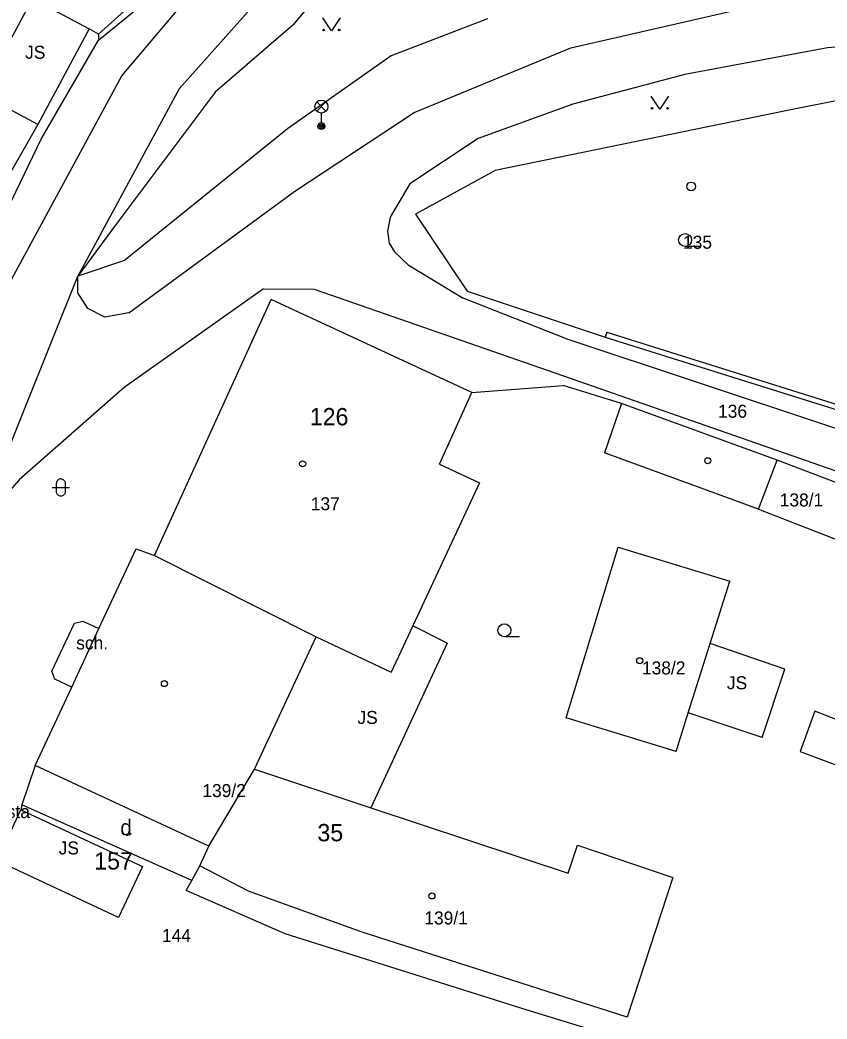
# Model space of a CAD drawing. Extents: x -836739 to -835945, y -1070775 to -1070126.
# Drawn here: x -836621.5 to -836574.9, y -1070420 to -1070362.4 of the extents above; entities that cross this region are included whole.
import ezdxf

# ---------------------------------------------------------------- set-up
doc = ezdxf.new("R2010")
doc.units = 0
for name, color, linetype in [('BodPole_mer', 7, 'Continuous'), ('Budovy_hranice', 7, 'Continuous'), ('Budovy_kody', 7, 'Continuous'), ('Doprava_hranice', 7, 'Continuous'), ('Doprava_kody', 7, 'Continuous'), ('OstPloch_hranice', 7, 'Continuous'), ('OstPloch_kody', 7, 'Continuous'), ('PovrZnIS_body', 7, 'Continuous'), ('RuianAdr_popis', 7, 'Continuous'), ('RuianPar_popis', 7, 'Continuous'), ('Stavby_hr_schod', 7, 'Continuous'), ('Stavby_hr_stav', 7, 'Continuous'), ('Stavby_kody', 7, 'Continuous'), ('Stavby_linie', 7, 'Continuous'), ('Zelen_kody', 7, 'Continuous')]:
    doc.layers.add(name, color=color, linetype=linetype)

msp = doc.modelspace()

# ---------------------------------------------------------------- linework, layer by layer
at = {"layer": 'BodPole_mer'}
for p, q in [((-836617.48, -1070362.88), (-836617.48, -1070362.88)), ((-836605.7, -1070362.64), (-836605.7, -1070362.64)), ((-836617.61, -1070363.13), (-836617.61, -1070363.13)), ((-836616.94, -1070363.17), (-836616.94, -1070363.17)), ((-836616.94, -1070363.53), (-836616.94, -1070363.53)), ((-836589.69, -1070363.97), (-836589.69, -1070363.97)), ((-836600.06, -1070364.43), (-836600.06, -1070364.43)), ((-836615.6, -1070365.58), (-836615.6, -1070365.58)), ((-836583.1, -1070365.51), (-836583.1, -1070365.51)), ((-836612.29, -1070366.34), (-836612.29, -1070366.34)), ((-836610.22, -1070366.53), (-836610.22, -1070366.53)), ((-836598.73, -1070367.69), (-836598.73, -1070367.69)), ((-836589.57, -1070367.22), (-836589.57, -1070367.22)), ((-836577.37, -1070367.63), (-836577.37, -1070367.63)), ((-836620.44, -1070368.4), (-836620.44, -1070368.4)), ((-836606.04, -1070368.64), (-836606.04, -1070368.64)), ((-836604.08, -1070368.48), (-836604.08, -1070368.48)), ((-836620.25, -1070369.24), (-836620.25, -1070369.24)), ((-836595.04, -1070369.19), (-836595.04, -1070369.19)), ((-836594.06, -1070371.04), (-836594.06, -1070371.04)), ((-836605.62, -1070372.23), (-836605.62, -1070372.23)), ((-836598.97, -1070371.82), (-836598.97, -1070371.82)), ((-836582.74, -1070371.96), (-836582.74, -1070371.96)), ((-836600.12, -1070373.74), (-836600.12, -1070373.74)), ((-836598.65, -1070373.57), (-836598.65, -1070373.57)), ((-836615.99, -1070374.22), (-836615.99, -1070374.22)), ((-836600.26, -1070374.54), (-836600.26, -1070374.54)), ((-836600.16, -1070375.24), (-836600.16, -1070375.24)), ((-836599.87, -1070375.74), (-836599.87, -1070375.74)), ((-836615.44, -1070376.23), (-836615.44, -1070376.23)), ((-836599.07, -1070376.48), (-836599.07, -1070376.48)), ((-836618.13, -1070377.15), (-836618.13, -1070377.15)), ((-836618.13, -1070378.1), (-836618.13, -1070378.1)), ((-836607.42, -1070377.87), (-836607.42, -1070377.87)), ((-836604.5, -1070377.9), (-836604.5, -1070377.9)), ((-836595.66, -1070378.01), (-836595.66, -1070378.01)), ((-836606.98, -1070378.49), (-836606.98, -1070378.49)), ((-836595.9, -1070378.41), (-836595.9, -1070378.41)), ((-836617.56, -1070379.01), (-836617.56, -1070379.01)), ((-836615.19, -1070379.26), (-836615.19, -1070379.26)), ((-836616.58, -1070379.5), (-836616.58, -1070379.5)), ((-836587.61, -1070380.37), (-836587.61, -1070380.37)), ((-836589.83, -1070380.79), (-836589.83, -1070380.79)), ((-836587.7, -1070380.66), (-836587.7, -1070380.66)), ((-836590.11, -1070382.9), (-836590.11, -1070382.9)), ((-836615.46, -1070383.56), (-836615.46, -1070383.56)), ((-836595.39, -1070383.86), (-836595.39, -1070383.86)), ((-836590.12, -1070383.45), (-836590.12, -1070383.45)), ((-836586.76, -1070384.49), (-836586.76, -1070384.49)), ((-836587.74, -1070387.34), (-836587.74, -1070387.34)), ((-836577.78, -1070387.76), (-836577.78, -1070387.76)), ((-836597.27, -1070387.99), (-836597.27, -1070387.99)), ((-836594.95, -1070389.07), (-836594.95, -1070389.07)), ((-836578.85, -1070390.58), (-836578.85, -1070390.58)), ((-836614.77, -1070392.87), (-836614.77, -1070392.87)), ((-836586.96, -1070392.78), (-836586.96, -1070392.78)), ((-836613.72, -1070393.26), (-836613.72, -1070393.26)), ((-836580.5, -1070394.75), (-836580.5, -1070394.75)), ((-836617.84, -1070397.05), (-836617.84, -1070397.05)), ((-836618.33, -1070397.16), (-836618.33, -1070397.16)), ((-836616.92, -1070397.47), (-836616.92, -1070397.47)), ((-836598.8, -1070397.31), (-836598.8, -1070397.31)), ((-836604.39, -1070397.96), (-836604.39, -1070397.96)), ((-836596.82, -1070398.31), (-836596.82, -1070398.31)), ((-836581.64, -1070398.34), (-836581.64, -1070398.34)), ((-836619.63, -1070399.94), (-836619.63, -1070399.94)), ((-836600.05, -1070399.99), (-836600.05, -1070399.99)), ((-836577.33, -1070399.82), (-836577.33, -1070399.82)), ((-836619.47, -1070400.39), (-836619.47, -1070400.39)), ((-836618.49, -1070400.85), (-836618.49, -1070400.85)), ((-836575.61, -1070402.24), (-836575.61, -1070402.24)), ((-836589.95, -1070402.63), (-836589.95, -1070402.63)), ((-836582.91, -1070402.34), (-836582.91, -1070402.34)), ((-836578.65, -1070403.77), (-836578.65, -1070403.77)), ((-836583.61, -1070404.56), (-836583.61, -1070404.56)), ((-836576.45, -1070404.57), (-836576.45, -1070404.57)), ((-836620.6, -1070405.38), (-836620.6, -1070405.38)), ((-836607.95, -1070405.59), (-836607.95, -1070405.59)), ((-836621.42, -1070407.93), (-836621.42, -1070407.93)), ((-836621.36, -1070407.64), (-836621.36, -1070407.64)), ((-836601.23, -1070407.82), (-836601.23, -1070407.82)), ((-836610.58, -1070410.04), (-836610.58, -1070410.04)), ((-836589.3, -1070409.98), (-836589.3, -1070409.98)), ((-836592.75, -1070410.62), (-836592.75, -1070410.62)), ((-836592.46, -1070410.72), (-836592.46, -1070410.72)), ((-836614.41, -1070411.21), (-836614.41, -1070411.21)), ((-836611.1, -1070411.16), (-836611.1, -1070411.16)), ((-836611.56, -1070412.01), (-836611.56, -1070412.01)), ((-836589.84, -1070411.58), (-836589.84, -1070411.58)), ((-836583.79, -1070411.84), (-836583.79, -1070411.84)), ((-836611.88, -1070412.58), (-836611.88, -1070412.58)), ((-836608.28, -1070412.62), (-836608.28, -1070412.62)), ((-836615.78, -1070414.14), (-836615.78, -1070414.14)), ((-836601.79, -1070414.98), (-836601.79, -1070414.98)), ((-836606.18, -1070415.08), (-836606.18, -1070415.08)), ((-836592.27, -1070419.48), (-836592.27, -1070419.48)), ((-836586.43, -1070419.9), (-836586.43, -1070419.9))]:
    msp.add_line(p, q, dxfattribs=at)
at = {"layer": 'Budovy_hranice'}
for p, q in [((-836613.72, -1070393.26), (-836606.98, -1070378.49)), ((-836595.39, -1070383.86), (-836606.98, -1070378.49)), ((-836597.27, -1070387.99), (-836595.39, -1070383.86)), ((-836586.76, -1070384.49), (-836587.74, -1070387.34)), ((-836577.78, -1070387.76), (-836586.76, -1070384.49)), ((-836578.85, -1070390.58), (-836587.74, -1070387.34)), ((-836578.85, -1070390.58), (-836577.78, -1070387.76)), ((-836566.92, -1070391.9), (-836577.78, -1070387.76)), ((-836597.27, -1070387.99), (-836594.95, -1070389.07)), ((-836589.95, -1070402.63), (-836586.96, -1070392.78)), ((-836586.96, -1070392.78), (-836580.5, -1070394.75)), ((-836604.39, -1070397.96), (-836600.05, -1070399.99)), ((-836583.61, -1070404.56), (-836589.95, -1070402.63)), ((-836589.84, -1070411.58), (-836589.3, -1070409.98)), ((-836589.3, -1070409.98), (-836583.79, -1070411.84)), ((-836583.79, -1070411.84), (-836586.43, -1070419.9)), ((-836601.79, -1070414.98), (-836608.28, -1070412.62)), ((-836586.43, -1070419.9), (-836601.79, -1070414.98))]:
    msp.add_line(p, q, dxfattribs=at)
for points in [[(-836594.95, -1070389.07), (-836598.8, -1070397.31), (-836600.05, -1070399.99)], [(-836578.85, -1070390.58), (-836572.88, -1070392.92), (-836567.83, -1070394.89)], [(-836610.58, -1070410.04), (-836620.6, -1070405.38), (-836618.49, -1070400.85), (-836616.92, -1070397.47), (-836614.77, -1070392.87), (-836613.72, -1070393.26), (-836604.39, -1070397.96)], [(-836583.61, -1070404.56), (-836582.91, -1070402.34), (-836581.64, -1070398.34), (-836580.5, -1070394.75)], [(-836608.28, -1070412.62), (-836611.1, -1070411.16), (-836610.58, -1070410.04), (-836607.95, -1070405.59), (-836604.39, -1070397.96)], [(-836570.76, -1070404.11), (-836574.08, -1070402.83), (-836575.61, -1070402.24), (-836576.45, -1070404.57), (-836571.47, -1070406.44), (-836570.76, -1070404.11)], [(-836607.95, -1070405.59), (-836601.23, -1070407.82), (-836592.75, -1070410.62), (-836592.46, -1070410.72), (-836589.84, -1070411.58)]]:
    msp.add_lwpolyline(points, dxfattribs=at)
at = {"layer": 'Budovy_kody'}
for centre in [(-836605.16, -1070387.97), (-836581.78, -1070387.79), (-836585.71, -1070399.33), (-836613.14, -1070400.65), (-836597.7, -1070412.9)]:
    msp.add_circle(centre, 0.175, dxfattribs=at)
at = {"layer": 'Doprava_hranice'}
msp.add_line((-836624, -1070391.72), (-836618.13, -1070377.15), dxfattribs=at)
for points in [[(-836637.13, -1070410.36), (-836632.54, -1070399.93), (-836624.1, -1070381.23), (-836615.6, -1070365.58), (-836607.14, -1070355.56), (-836596.81, -1070346.2), (-836590.03, -1070339.5), (-836589.31, -1070338.79), (-836589.07, -1070337.69), (-836589.06, -1070336.43), (-836589.28, -1070334.96), (-836590.73, -1070333.14), (-836591.73, -1070332.35), (-836593.66, -1070331.61), (-836605.86, -1070329.36), (-836624.31, -1070324.48)], [(-836615.19, -1070379.26), (-836605.62, -1070372.23), (-836598.73, -1070367.69), (-836589.69, -1070363.97), (-836577.99, -1070361.29), (-836567.54, -1070359.78), (-836561.76, -1070359.47), (-836555.57, -1070359.6), (-836542.56, -1070361.3), (-836539.53, -1070361.13), (-836537.36, -1070360.46), (-836536.61, -1070359.71), (-836537.63, -1070358), (-836543.83, -1070354.6), (-836550.65, -1070351.53), (-836553.41, -1070349.94), (-836556.85, -1070346.77), (-836557.71, -1070345.9), (-836560.14, -1070342.4), (-836564.87, -1070335.97), (-836569.41, -1070333.94)], [(-836589.25, -1070343.85), (-836600.64, -1070354.35), (-836606.73, -1070360.09), (-836612.29, -1070366.34), (-836618.13, -1070377.15)], [(-836599.6, -1070356.75), (-836602.09, -1070358.28), (-836605.7, -1070362.64), (-836610.22, -1070366.53), (-836615.99, -1070374.22), (-836618.13, -1070377.15)], [(-836594.49, -1070362.3), (-836600.06, -1070364.43), (-836606.04, -1070368.64), (-836615.44, -1070376.23), (-836618.13, -1070377.15)], [(-836547.65, -1070364.49), (-836556.3, -1070362.82), (-836560.36, -1070362.88), (-836566.97, -1070363.32), (-836574.87, -1070363.96), (-836583.1, -1070365.51), (-836589.57, -1070367.22), (-836595.04, -1070369.19), (-836598.97, -1070371.82)], [(-836598.97, -1070371.82), (-836600.12, -1070373.74), (-836600.26, -1070374.54), (-836600.16, -1070375.24), (-836599.87, -1070375.74), (-836599.07, -1070376.48), (-836595.9, -1070378.41)], [(-836615.19, -1070379.26), (-836616.58, -1070379.5), (-836617.56, -1070379.01), (-836618.13, -1070378.1), (-836618.13, -1070377.15)], [(-836607.42, -1070377.87), (-836615.46, -1070383.56), (-836621.52, -1070388.89), (-836624, -1070391.72)], [(-836607.42, -1070377.87), (-836604.5, -1070377.9), (-836590.11, -1070382.9), (-836566.68, -1070391.06)], [(-836567.33, -1070388.27), (-836589.83, -1070380.79), (-836595.9, -1070378.41)]]:
    msp.add_lwpolyline(points, dxfattribs=at)
at = {"layer": 'OstPloch_hranice'}
msp.add_line((-836620.6, -1070405.38), (-836621.36, -1070407.64), dxfattribs=at)
at = {"layer": 'OstPloch_kody'}
for p, q in [((-836582.215, -1070375.43), (-836583.09, -1070375.43)), ((-836619.62, -1070389.34), (-836618.62, -1070389.34)), ((-836619.37, -1070389.59), (-836619.37, -1070389.09)), ((-836618.87, -1070389.09), (-836618.87, -1070389.59)), ((-836592.645, -1070397.95), (-836593.52, -1070397.95))]:
    msp.add_line(p, q, dxfattribs=at)
for points in [[(-836619.12, -1070388.84), (-836619.165, -1070388.844), (-836619.212, -1070388.858), (-836619.257, -1070388.881), (-836619.297, -1070388.913), (-836619.329, -1070388.953), (-836619.352, -1070388.998), (-836619.366, -1070389.045), (-836619.37, -1070389.09)], [(-836619.12, -1070388.84), (-836619.075, -1070388.844), (-836619.028, -1070388.858), (-836618.983, -1070388.881), (-836618.943, -1070388.913), (-836618.911, -1070388.953), (-836618.888, -1070388.998), (-836618.874, -1070389.045), (-836618.87, -1070389.09)], [(-836619.12, -1070389.84), (-836619.165, -1070389.836), (-836619.212, -1070389.822), (-836619.257, -1070389.799), (-836619.297, -1070389.767), (-836619.329, -1070389.727), (-836619.352, -1070389.682), (-836619.366, -1070389.635), (-836619.37, -1070389.59)], [(-836618.87, -1070389.59), (-836618.874, -1070389.635), (-836618.888, -1070389.682), (-836618.911, -1070389.727), (-836618.943, -1070389.767), (-836618.983, -1070389.799), (-836619.028, -1070389.822), (-836619.075, -1070389.836), (-836619.12, -1070389.84)], [(-836615.309, -1070409.4), (-836615.309, -1070409.405), (-836615.308, -1070409.411), (-836615.3, -1070409.415), (-836615.283, -1070409.413), (-836615.253, -1070409.404), (-836615.205, -1070409.383), (-836615.137, -1070409.347), (-836615.044, -1070409.294)]]:
    msp.add_lwpolyline(points, dxfattribs=at)
for centre in [(-836583.09, -1070375.055), (-836593.52, -1070397.575)]:
    msp.add_ellipse(centre, major_axis=(0.375, 0), ratio=0.999999, dxfattribs=at)
at = {"layer": 'PovrZnIS_body'}
for p, q in [((-836604.345, -1070367.62), (-836603.815, -1070367.09)), ((-836604.345, -1070367.09), (-836603.815, -1070367.62)), ((-836604.08, -1070368.28), (-836604.08, -1070367.73))]:
    msp.add_line(p, q, dxfattribs=at)
msp.add_circle((-836582.74, -1070371.96), 0.25, dxfattribs=at)
for centre, major_axis in [((-836604.08, -1070367.355), (0.375, 0)), ((-836604.08, -1070368.48), (0.2, 0)), ((-836604.076, -1070368.48), (0.125, 0)), ((-836604.076, -1070368.48), (0.05, 0))]:
    msp.add_ellipse(centre, major_axis=major_axis, ratio=0.999998, dxfattribs=at)
at = {"layer": 'RuianAdr_popis'}
for p, q in [((-836604.75, -1070385.75), (-836604.75, -1070385.75)), ((-836604.31, -1070409.75), (-836604.31, -1070409.75)), ((-836617.19, -1070411.38), (-836617.19, -1070411.38))]:
    msp.add_line(p, q, dxfattribs=at)
at = {"layer": 'RuianPar_popis'}
for p, q in [((-836583.21, -1070375.56), (-836583.21, -1070375.56)), ((-836581.19, -1070385.31), (-836581.19, -1070385.31)), ((-836604.69, -1070390.65), (-836604.69, -1070390.65)), ((-836577.63, -1070390.43), (-836577.63, -1070390.43)), ((-836585.58, -1070400.12), (-836585.58, -1070400.12)), ((-836610.95, -1070407.2), (-836610.95, -1070407.2)), ((-836598.14, -1070414.55), (-836598.14, -1070414.55)), ((-836613.28, -1070415.56), (-836613.28, -1070415.56))]:
    msp.add_line(p, q, dxfattribs=at)
at = {"layer": 'Stavby_hr_schod'}
msp.add_lwpolyline([(-836618.49, -1070400.85), (-836619.47, -1070400.39), (-836619.63, -1070399.94), (-836618.33, -1070397.16), (-836617.84, -1070397.05), (-836616.92, -1070397.47)], dxfattribs=at)
at = {"layer": 'Stavby_hr_stav'}
for p, q in [((-836587.7, -1070380.66), (-836567.64, -1070386.96)), ((-836596.82, -1070398.31), (-836598.8, -1070397.31)), ((-836596.82, -1070398.31), (-836601.23, -1070407.82)), ((-836578.65, -1070403.77), (-836582.91, -1070402.34))]:
    msp.add_line(p, q, dxfattribs=at)
for points in [[(-836620.44, -1070368.4), (-836623.72, -1070366.64), (-836620.75, -1070361.12), (-836620.48, -1070361.27), (-836617.48, -1070362.88), (-836617.61, -1070363.13), (-836620.44, -1070368.4)], [(-836578.65, -1070403.77), (-836577.33, -1070399.82), (-836581.64, -1070398.34)], [(-836621.42, -1070407.93), (-836614.41, -1070411.21), (-836615.78, -1070414.14), (-836622.8, -1070410.87), (-836621.81, -1070408.77), (-836621.42, -1070407.93)]]:
    msp.add_lwpolyline(points, dxfattribs=at)
at = {"layer": 'Stavby_linie'}
for p, q in [((-836616.94, -1070363.17), (-836617.48, -1070362.88)), ((-836587.61, -1070380.37), (-836587.7, -1070380.66)), ((-836587.61, -1070380.37), (-836567.72, -1070386.62)), ((-836595.39, -1070383.86), (-836590.12, -1070383.45)), ((-836586.76, -1070384.49), (-836590.12, -1070383.45))]:
    msp.add_line(p, q, dxfattribs=at)
for points in [[(-836608.79, -1070352.5), (-836611.63, -1070356.68), (-836613.95, -1070360.46), (-836616.94, -1070363.17), (-836616.94, -1070363.53)], [(-836616.94, -1070363.53), (-836613.84, -1070360.99), (-836608.56, -1070352.7)], [(-836626.49, -1070382.25), (-836624.37, -1070377.75), (-836620.25, -1070369.24), (-836616.94, -1070363.53)], [(-836573.6, -1070366.88), (-836577.37, -1070367.63), (-836594.06, -1070371.04), (-836598.65, -1070373.57), (-836595.66, -1070378.01), (-836587.7, -1070380.66)], [(-836620.44, -1070368.4), (-836622.88, -1070372.65), (-836625.16, -1070377.26)], [(-836611.56, -1070412.01), (-836621.36, -1070407.64), (-836621.42, -1070407.93)], [(-836574.93, -1070422.97), (-836582.62, -1070420.71), (-836583.02, -1070422.31), (-836592.27, -1070419.48), (-836606.18, -1070415.08), (-836611.88, -1070412.58), (-836611.56, -1070412.01), (-836611.1, -1070411.16)]]:
    msp.add_lwpolyline(points, dxfattribs=at)
at = {"layer": 'Zelen_kody'}
for points in [[(-836603, -1070362.24), (-836603.5, -1070362.99), (-836604, -1070362.24)], [(-836584.05, -1070366.76), (-836584.55, -1070367.51), (-836585.05, -1070366.76)]]:
    msp.add_lwpolyline(points, dxfattribs=at)
for centre in [(-836603.949, -1070362.94), (-836603.049, -1070362.94), (-836584.999, -1070367.46), (-836584.099, -1070367.46)]:
    msp.add_circle(centre, 0.05, dxfattribs=at)

# ---------------------------------------------------------------- texts
at = {"layer": 'Doprava_kody'}
msp.add_text('nezp.cesta', height=0.75, dxfattribs=at).set_placement((-836625.75, -1070408.41))
at = {"layer": 'OstPloch_kody'}
msp.add_text('d', height=0.9, dxfattribs=at).set_placement((-836615.685, -1070409.4))
at = {"layer": 'RuianAdr_popis'}
for s, p in [('126', (-836604.75, -1070385.75)), ('35', (-836604.31, -1070409.75)), ('157', (-836617.19, -1070411.38))]:
    msp.add_text(s, height=1, dxfattribs=at).set_placement(p)
at = {"layer": 'RuianPar_popis'}
for s, p in [('135', (-836583.21, -1070375.56)), ('136', (-836581.19, -1070385.31)), ('138/1', (-836577.63, -1070390.43)), ('137', (-836604.69, -1070390.65)), ('138/2', (-836585.58, -1070400.12)), ('139/2', (-836610.95, -1070407.2)), ('139/1', (-836598.14, -1070414.55)), ('144', (-836613.28, -1070415.56))]:
    msp.add_text(s, height=0.75, dxfattribs=at).set_placement(p)
at = {"layer": 'Stavby_kody'}
for s, p in [('JS', (-836621.18, -1070364.6)), ('sch.', (-836618.23, -1070398.68)), ('JS', (-836580.68, -1070400.98)), ('JS', (-836602, -1070402.98)), ('JS', (-836619.24, -1070410.51))]:
    msp.add_text(s, height=0.75, dxfattribs=at).set_placement(p)

doc.saveas('drawing.dxf')
